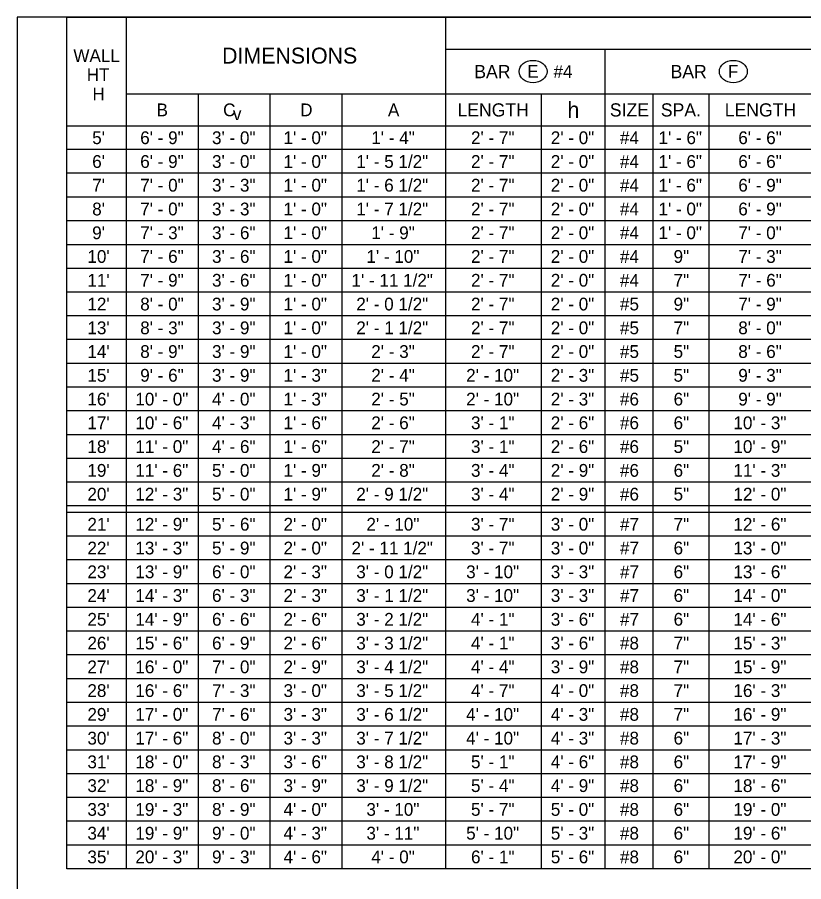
# Model space of a CAD drawing. Extents: x 99862 to 103151, y 100000 to 105076.
# Drawn here: x 99862 to 100848, y 103992 to 105076 of the extents above; entities that cross this region are included whole.
import ezdxf

# ---------------------------------------------------------------- set-up
doc = ezdxf.new("R2010")
doc.units = 0
for name, color, linetype in [('Level 1', 7, 'Continuous'), ('Level 20', 7, 'Continuous'), ('Level 4', 7, 'Continuous')]:
    doc.layers.add(name, color=color, linetype=linetype)

msp = doc.modelspace()

# ---------------------------------------------------------------- linework, layer by layer
at = {"layer": 'Level 1'}
msp.add_lwpolyline([(99862, 102999.5), (103151, 102999.5), (103151, 105075.5), (99862, 105075.5)], close=True, dxfattribs=at)
at = {"layer": 'Level 20'}
for centre in [(100508.5, 105007.5), (100759.5, 105007.5)]:
    msp.add_ellipse(centre, major_axis=(-17.5, 0), ratio=0.8, dxfattribs=at)
at = {"layer": 'Level 4'}
for p, q in [((99999, 104008.6), (99999, 105075.5)), ((100399, 104008.6), (100399, 105075.5)), ((100399, 105035.5), (102539, 105035.5)), ((100599, 104008.6), (100599, 105035.5)), ((99999, 104979.5), (102711, 104979.5)), ((100089, 104008.6), (100089, 104979.5)), ((100179, 104008.6), (100179, 104979.5)), ((100269, 104008.6), (100269, 104979.5)), ((100519, 104008.6), (100519, 104979.5)), ((100659, 104008.6), (100659, 104979.5)), ((100729, 104008.6), (100729, 104979.5)), ((99924, 104939.5), (103151, 104939.5)), ((103151, 104909.7), (99924, 104909.7)), ((103151, 104880), (99924, 104880)), ((103151, 104850.2), (99924, 104850.2)), ((103151, 104820.4), (99924, 104820.4)), ((103151, 104790.6), (99924, 104790.6)), ((103151, 104760.9), (99924, 104760.9)), ((103151, 104731.1), (99924, 104731.1)), ((103151, 104701.3), (99924, 104701.3)), ((103151, 104671.6), (99924, 104671.6)), ((103151, 104641.8), (99924, 104641.8)), ((103151, 104612), (99924, 104612)), ((103151, 104582.2), (99924, 104582.2)), ((103151, 104552.5), (99924, 104552.5)), ((103151, 104522.7), (99924, 104522.7)), ((103151, 104492.9), (99924, 104492.9)), ((103151, 104463.2), (99924, 104463.2)), ((103151, 104455.2), (99924, 104455.2)), ((103151, 104425.4), (99924, 104425.4)), ((103151, 104395.6), (99924, 104395.6)), ((103151, 104365.8), (99924, 104365.8)), ((103151, 104336.1), (99924, 104336.1)), ((103151, 104306.3), (99924, 104306.3)), ((103151, 104276.5), (99924, 104276.5)), ((103151, 104246.8), (99924, 104246.8)), ((103151, 104217), (99924, 104217)), ((103151, 104187.2), (99924, 104187.2)), ((103151, 104157.4), (99924, 104157.4)), ((103151, 104127.7), (99924, 104127.7)), ((103151, 104097.9), (99924, 104097.9)), ((103151, 104068.1), (99924, 104068.1)), ((103151, 104038.4), (99924, 104038.4))]:
    msp.add_line(p, q, dxfattribs=at)
for points in [[(99924, 105075.5), (103151, 105075.5)], [(103151, 104008.6), (99924, 104008.6), (99924, 105075.5)]]:
    msp.add_lwpolyline(points, dxfattribs=at)

# ---------------------------------------------------------------- texts
at = {"layer": 'Level 20'}
for s, height, p in [('WALL', 16, (99932.3, 105019.5)), ('DIMENSIONS', 20, (100118.7, 105017.5)), ('HT', 16, (99949.1, 104995.5)), ('BAR', 16.5, (100434.8, 104999.2)), ('E', 16, (100501.1, 104999.7)), ('#4', 16, (100534, 104999.5)), ('BAR', 16.5, (100680.8, 104999.2)), ('F', 16, (100752.7, 104999.7)), ('H', 16, (99956.2, 104971.5)), ('B', 16, (100036.6, 104951.5)), ('C', 16, (100120, 104951.5)), ('D', 16, (100216.6, 104951.5)), ('A', 16, (100326.6, 104951.5)), ('LENGTH', 16.5, (100413.7, 104951.2)), ('h', 20, (100551.6, 104949.5)), ('SIZE', 16.5, (100604.7, 104951.2)), ('SPA.', 16.5, (100668.6, 104951.2)), ('LENGTH', 16.5, (100748.7, 104951.2)), ('v', 16, (100132.3, 104946.6)), ("5'", 16, (99955.9, 104916.6)), ("6'", 16, (99955.9, 104886.8)), ("7'", 16, (99955.9, 104857.1)), ("8'", 16, (99955.9, 104827.3)), ("9'", 16, (99955.9, 104797.5)), ("10'", 16, (99949.9, 104767.8)), ("11'", 16, (99949.9, 104738)), ("12'", 16, (99949.9, 104708.2)), ("13'", 16, (99949.9, 104678.4)), ("14'", 16, (99949.9, 104648.7)), ("15'", 16, (99949.9, 104618.9)), ("16'", 16, (99949.9, 104589.1)), ("17'", 16, (99949.9, 104559.4)), ("18'", 16, (99949.9, 104529.6)), ("19'", 16, (99949.9, 104499.8)), ("20'", 16, (99949.9, 104470)), ("21'", 16, (99949.9, 104432.3)), ("22'", 16, (99949.9, 104402.5)), ("23'", 16, (99949.9, 104372.7)), ("24'", 16, (99949.9, 104343)), ("25'", 16, (99949.9, 104313.2)), ("26'", 16, (99949.9, 104283.4)), ("27'", 16, (99949.9, 104253.6)), ("28'", 16, (99949.9, 104223.9)), ("29'", 16, (99949.9, 104194.1)), ("30'", 16, (99949.9, 104164.3)), ("31'", 16, (99949.9, 104134.6)), ("32'", 16, (99949.9, 104104.8)), ("33'", 16, (99949.9, 104075)), ("34'", 16, (99949.9, 104045.2)), ("35'", 16, (99949.9, 104015.5))]:
    msp.add_text(s, height=height, dxfattribs=at).set_placement(p)
at = {"layer": 'Level 4'}
for s, p in [('6\' - 9"', (100016.1, 104916.6)), ('3\' - 0"', (100106.1, 104916.6)), ('1\' - 0"', (100195.7, 104916.6)), ('1\' - 4"', (100305.7, 104916.6)), ('2\' - 7"', (100430.7, 104916.6)), ('2\' - 0"', (100530.7, 104916.6)), ('6\' - 9"', (100016.1, 104886.8)), ('3\' - 0"', (100106.1, 104886.8)), ('1\' - 0"', (100195.7, 104886.8)), ('1\' - 5 1/2"', (100286.9, 104886.8)), ('2\' - 7"', (100430.7, 104886.8)), ('2\' - 0"', (100530.7, 104886.8)), ('7\' - 0"', (100016.1, 104857.1)), ('3\' - 3"', (100106.1, 104857.1)), ('1\' - 0"', (100195.7, 104857.1)), ('1\' - 6 1/2"', (100286.9, 104857.1)), ('2\' - 7"', (100430.7, 104857.1)), ('2\' - 0"', (100530.7, 104857.1)), ('7\' - 0"', (100016.1, 104827.3)), ('3\' - 3"', (100106.1, 104827.3)), ('1\' - 0"', (100195.7, 104827.3)), ('1\' - 7 1/2"', (100286.9, 104827.3)), ('2\' - 7"', (100430.7, 104827.3)), ('2\' - 0"', (100530.7, 104827.3)), ('7\' - 3"', (100016.1, 104797.5)), ('3\' - 6"', (100106.1, 104797.5)), ('1\' - 0"', (100195.7, 104797.5)), ('1\' - 9"', (100305.7, 104797.5)), ('2\' - 7"', (100430.7, 104797.5)), ('2\' - 0"', (100530.7, 104797.5)), ('7\' - 6"', (100016.1, 104767.8)), ('3\' - 6"', (100106.1, 104767.8)), ('1\' - 0"', (100195.7, 104767.8)), ('1\' - 10"', (100299.6, 104767.8)), ('2\' - 7"', (100430.7, 104767.8)), ('2\' - 0"', (100530.7, 104767.8)), ('7\' - 9"', (100016.1, 104738)), ('3\' - 6"', (100106.1, 104738)), ('1\' - 0"', (100195.7, 104738)), ('1\' - 11 1/2"', (100280.9, 104738)), ('2\' - 7"', (100430.7, 104738)), ('2\' - 0"', (100530.7, 104738)), ('8\' - 0"', (100016.1, 104708.2)), ('3\' - 9"', (100106.1, 104708.2)), ('1\' - 0"', (100195.7, 104708.2)), ('2\' - 0 1/2"', (100286.9, 104708.2)), ('2\' - 7"', (100430.7, 104708.2)), ('2\' - 0"', (100530.7, 104708.2)), ('8\' - 3"', (100016.1, 104678.4)), ('3\' - 9"', (100106.1, 104678.4)), ('1\' - 0"', (100195.7, 104678.4)), ('2\' - 1 1/2"', (100286.9, 104678.4)), ('2\' - 7"', (100430.7, 104678.4)), ('2\' - 0"', (100530.7, 104678.4)), ('8\' - 9"', (100016.1, 104648.7)), ('3\' - 9"', (100106.1, 104648.7)), ('1\' - 0"', (100195.7, 104648.7)), ('2\' - 3"', (100305.7, 104648.7)), ('2\' - 7"', (100430.7, 104648.7)), ('2\' - 0"', (100530.7, 104648.7)), ('9\' - 6"', (100016.1, 104618.9)), ('3\' - 9"', (100106.1, 104618.9)), ('1\' - 3"', (100195.7, 104618.9)), ('2\' - 4"', (100305.7, 104618.9)), ('2\' - 10"', (100424.6, 104618.9)), ('2\' - 3"', (100530.7, 104618.9)), ('10\' - 0"', (100010, 104589.1)), ('4\' - 0"', (100106.1, 104589.1)), ('1\' - 3"', (100195.7, 104589.1)), ('2\' - 5"', (100305.7, 104589.1)), ('2\' - 10"', (100424.6, 104589.1)), ('2\' - 3"', (100530.7, 104589.1)), ('10\' - 6"', (100010, 104559.4)), ('4\' - 3"', (100106.1, 104559.4)), ('1\' - 6"', (100195.7, 104559.4)), ('2\' - 6"', (100305.7, 104559.4)), ('3\' - 1"', (100430.7, 104559.4)), ('2\' - 6"', (100530.7, 104559.4)), ('11\' - 0"', (100010, 104529.6)), ('4\' - 6"', (100106.1, 104529.6)), ('1\' - 6"', (100195.7, 104529.6)), ('2\' - 7"', (100305.7, 104529.6)), ('3\' - 1"', (100430.7, 104529.6)), ('2\' - 6"', (100530.7, 104529.6)), ('11\' - 6"', (100010, 104499.8)), ('5\' - 0"', (100106.1, 104499.8)), ('1\' - 9"', (100195.7, 104499.8)), ('2\' - 8"', (100305.7, 104499.8)), ('3\' - 4"', (100430.7, 104499.8)), ('2\' - 9"', (100530.7, 104499.8)), ('12\' - 3"', (100010, 104470)), ('5\' - 0"', (100106.1, 104470)), ('1\' - 9"', (100195.7, 104470)), ('2\' - 9 1/2"', (100286.9, 104470)), ('3\' - 4"', (100430.7, 104470)), ('2\' - 9"', (100530.7, 104470)), ('12\' - 9"', (100010, 104432.3)), ('5\' - 6"', (100106.1, 104432.3)), ('2\' - 0"', (100195.7, 104432.3)), ('2\' - 10"', (100299.6, 104432.3)), ('3\' - 7"', (100430.7, 104432.3)), ('3\' - 0"', (100530.7, 104432.3)), ('13\' - 3"', (100010, 104402.5)), ('5\' - 9"', (100106.1, 104402.5)), ('2\' - 0"', (100195.7, 104402.5)), ('2\' - 11 1/2"', (100280.9, 104402.5)), ('3\' - 7"', (100430.7, 104402.5)), ('3\' - 0"', (100530.7, 104402.5)), ('13\' - 9"', (100010, 104372.7)), ('6\' - 0"', (100106.1, 104372.7)), ('2\' - 3"', (100195.7, 104372.7)), ('3\' - 0 1/2"', (100286.9, 104372.7)), ('3\' - 10"', (100424.6, 104372.7)), ('3\' - 3"', (100530.7, 104372.7)), ('14\' - 3"', (100010, 104343)), ('6\' - 3"', (100106.1, 104343)), ('2\' - 3"', (100195.7, 104343)), ('3\' - 1 1/2"', (100286.9, 104343)), ('3\' - 10"', (100424.6, 104343)), ('3\' - 3"', (100530.7, 104343)), ('14\' - 9"', (100010, 104313.2)), ('6\' - 6"', (100106.1, 104313.2)), ('2\' - 6"', (100195.7, 104313.2)), ('3\' - 2 1/2"', (100286.9, 104313.2)), ('4\' - 1"', (100430.7, 104313.2)), ('3\' - 6"', (100530.7, 104313.2)), ('15\' - 6"', (100010, 104283.4)), ('6\' - 9"', (100106.1, 104283.4)), ('2\' - 6"', (100195.7, 104283.4)), ('3\' - 3 1/2"', (100286.9, 104283.4)), ('4\' - 1"', (100430.7, 104283.4)), ('3\' - 6"', (100530.7, 104283.4)), ('16\' - 0"', (100010, 104253.6)), ('7\' - 0"', (100106.1, 104253.6)), ('2\' - 9"', (100195.7, 104253.6)), ('3\' - 4 1/2"', (100286.9, 104253.6)), ('4\' - 4"', (100430.7, 104253.6)), ('3\' - 9"', (100530.7, 104253.6)), ('16\' - 6"', (100010, 104223.9)), ('7\' - 3"', (100106.1, 104223.9)), ('3\' - 0"', (100195.7, 104223.9)), ('3\' - 5 1/2"', (100286.9, 104223.9)), ('4\' - 7"', (100430.7, 104223.9)), ('4\' - 0"', (100530.7, 104223.9)), ('17\' - 0"', (100010, 104194.1)), ('7\' - 6"', (100106.1, 104194.1)), ('3\' - 3"', (100195.7, 104194.1)), ('3\' - 6 1/2"', (100286.9, 104194.1)), ('4\' - 10"', (100424.6, 104194.1)), ('4\' - 3"', (100530.7, 104194.1)), ('17\' - 6"', (100010, 104164.3)), ('8\' - 0"', (100106.1, 104164.3)), ('3\' - 3"', (100195.7, 104164.3)), ('3\' - 7 1/2"', (100286.9, 104164.3)), ('4\' - 10"', (100424.6, 104164.3)), ('4\' - 3"', (100530.7, 104164.3)), ('18\' - 0"', (100010, 104134.6)), ('8\' - 3"', (100106.1, 104134.6)), ('3\' - 6"', (100195.7, 104134.6)), ('3\' - 8 1/2"', (100286.9, 104134.6)), ('5\' - 1"', (100430.7, 104134.6)), ('4\' - 6"', (100530.7, 104134.6)), ('18\' - 9"', (100010, 104104.8)), ('8\' - 6"', (100106.1, 104104.8)), ('3\' - 9"', (100195.7, 104104.8)), ('3\' - 9 1/2"', (100286.9, 104104.8)), ('5\' - 4"', (100430.7, 104104.8)), ('4\' - 9"', (100530.7, 104104.8)), ('19\' - 3"', (100010, 104075)), ('8\' - 9"', (100106.1, 104075)), ('4\' - 0"', (100195.7, 104075)), ('3\' - 10"', (100299.6, 104075)), ('5\' - 7"', (100430.7, 104075)), ('5\' - 0"', (100530.7, 104075)), ('19\' - 9"', (100010, 104045.2)), ('9\' - 0"', (100106.1, 104045.2)), ('4\' - 3"', (100195.7, 104045.2)), ('3\' - 11"', (100299.6, 104045.2)), ('5\' - 10"', (100424.6, 104045.2)), ('5\' - 3"', (100530.7, 104045.2)), ('20\' - 3"', (100010, 104015.5)), ('9\' - 3"', (100106.1, 104015.5)), ('4\' - 6"', (100195.7, 104015.5)), ('4\' - 0"', (100305.7, 104015.5)), ('6\' - 1"', (100430.7, 104015.5)), ('5\' - 6"', (100530.7, 104015.5))]:
    msp.add_text(s, height=16, dxfattribs=at).set_placement(p)
for s, p in [('#4', (100617.4, 104916.6)), ('1\' - 6"', (100665.7, 104916.6)), ('6\' - 6"', (100765.7, 104916.6)), ('#4', (100617.4, 104886.8)), ('1\' - 6"', (100665.7, 104886.8)), ('6\' - 6"', (100765.7, 104886.8)), ('#4', (100617.4, 104857.1)), ('1\' - 6"', (100665.7, 104857.1)), ('6\' - 9"', (100765.7, 104857.1)), ('#4', (100617.4, 104827.3)), ('1\' - 0"', (100665.7, 104827.3)), ('6\' - 9"', (100765.7, 104827.3)), ('#4', (100617.4, 104797.5)), ('1\' - 0"', (100665.7, 104797.5)), ('7\' - 0"', (100765.7, 104797.5)), ('#4', (100617.4, 104767.8)), ('9"', (100684.6, 104767.8)), ('7\' - 3"', (100765.7, 104767.8)), ('#4', (100617.4, 104738)), ('7"', (100684.6, 104738)), ('7\' - 6"', (100765.7, 104738)), ('#5', (100617.4, 104708.2)), ('9"', (100684.6, 104708.2)), ('7\' - 9"', (100765.7, 104708.2)), ('#5', (100617.4, 104678.4)), ('7"', (100684.6, 104678.4)), ('8\' - 0"', (100765.7, 104678.4)), ('#5', (100617.4, 104648.7)), ('5"', (100684.6, 104648.7)), ('8\' - 6"', (100765.7, 104648.7)), ('#5', (100617.4, 104618.9)), ('5"', (100684.6, 104618.9)), ('9\' - 3"', (100765.7, 104618.9)), ('#6', (100617.4, 104589.1)), ('6"', (100684.6, 104589.1)), ('9\' - 9"', (100765.7, 104589.1)), ('#6', (100617.4, 104559.4)), ('6"', (100684.6, 104559.4)), ('10\' - 3"', (100759.6, 104559.4)), ('#6', (100617.4, 104529.6)), ('5"', (100684.6, 104529.6)), ('10\' - 9"', (100759.6, 104529.6)), ('#6', (100617.4, 104499.8)), ('6"', (100684.6, 104499.8)), ('11\' - 3"', (100759.6, 104499.8)), ('#6', (100617.4, 104470)), ('5"', (100684.6, 104470)), ('12\' - 0"', (100759.6, 104470)), ('#7', (100617.5, 104432.3)), ('7"', (100684.6, 104432.3)), ('12\' - 6"', (100759.6, 104432.3)), ('#7', (100617.5, 104402.5)), ('6"', (100684.6, 104402.5)), ('13\' - 0"', (100759.6, 104402.5)), ('#7', (100617.5, 104372.7)), ('6"', (100684.6, 104372.7)), ('13\' - 6"', (100759.6, 104372.7)), ('#7', (100617.5, 104343)), ('6"', (100684.6, 104343)), ('14\' - 0"', (100759.6, 104343)), ('#7', (100617.5, 104313.2)), ('6"', (100684.6, 104313.2)), ('14\' - 6"', (100759.6, 104313.2)), ('#8', (100617.4, 104283.4)), ('7"', (100684.6, 104283.4)), ('15\' - 3"', (100759.6, 104283.4)), ('#8', (100617.4, 104253.6)), ('7"', (100684.6, 104253.6)), ('15\' - 9"', (100759.6, 104253.6)), ('#8', (100617.4, 104223.9)), ('7"', (100684.6, 104223.9)), ('16\' - 3"', (100759.6, 104223.9)), ('#8', (100617.4, 104194.1)), ('7"', (100684.6, 104194.1)), ('16\' - 9"', (100759.6, 104194.1)), ('#8', (100617.4, 104164.3)), ('6"', (100684.6, 104164.3)), ('17\' - 3"', (100759.6, 104164.3)), ('#8', (100617.4, 104134.6)), ('6"', (100684.6, 104134.6)), ('17\' - 9"', (100759.6, 104134.6)), ('#8', (100617.4, 104104.8)), ('6"', (100684.6, 104104.8)), ('18\' - 6"', (100759.6, 104104.8)), ('#8', (100617.4, 104075)), ('6"', (100684.6, 104075)), ('19\' - 0"', (100759.6, 104075)), ('#8', (100617.4, 104045.2)), ('6"', (100684.6, 104045.2)), ('19\' - 6"', (100759.6, 104045.2)), ('#8', (100617.4, 104015.5)), ('6"', (100684.6, 104015.5)), ('20\' - 0"', (100759.6, 104015.5))]:
    msp.add_text(s, height=16, rotation=360, dxfattribs=at).set_placement(p)

doc.saveas('drawing.dxf')
